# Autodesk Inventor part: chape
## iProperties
Shininess: 64.0
Length Units: 11269
Angle Units: 11279
Time Units: 11290
Mass Units: 11283
Length Display Precision: 3
Angle Display Precision: 2
Compacted: True
Part Number: chape
Document SubType Name: Modeling
Created: 2004-12
Material: Par défaut
Designer: LEGERET Philippe
Density: 0.0
Volumn: 0.0
Area: 0.0
PropertySet Name: Model Information
Control State: 0
Master: False
Checked Out: False
Author: LEGERET Philippe
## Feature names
1. Extrusion1
2. Perçage1 [Hole]
